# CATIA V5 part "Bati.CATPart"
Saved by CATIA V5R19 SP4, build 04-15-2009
Part number: Bati
Bounding box of the stored display mesh (mm): x 0 to 10, y 41.42 to 122.58, z 0 to 71.818
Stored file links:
  C:\Users\rcousturie\Desktop\EU_thinkMotion\iao\IAO_MMS_Groupe1\abergami\abergami_catiaInitial\ObjetsInitials\Bati.CATPart
  C:\Users\rcousturie\Desktop\EU_thinkMotion\iao\IAO_MMS_Groupe1\abergami\abergami_catiaInitial\ObjetsInitials\Product2.CATProduct
  C:\Users\rcousturie\Desktop\EU_thinkMotion\iao\IAO_MMS_Groupe1\abergami\abergami_catiaInitial\ObjetsInitials\Squelettedebase.CATPart
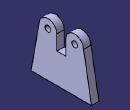
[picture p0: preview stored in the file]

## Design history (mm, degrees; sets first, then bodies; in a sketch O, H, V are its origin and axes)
External parameters (linked from other documents)
  External.Hauteursaxesbati = 60 mm
Set1
  Point1: linked copy from another document
  Point2: linked copy from another document
Body1 (main body)
  Sketch1 on yz-plane, origin (0, 0, 0), H (0, 1, 0), V (0, 0, 1)
    arc A1 centre (100, 60) radius 12 from (112, 60) to (88, 60) ccw
    point P1 (100, 60)
    arc A2 centre (64, 60) radius 12 from (76, 60) to (52, 60) ccw
    point P2 (64, 60)
    reference projected point E1 (100, 60) from Point1
    reference projected point E2 (64, 60) from Point2
    line L1 (76, 60) -> (76, 40)
    line L2 (76, 40) -> (88, 40)
    line L3 (88, 60) -> (88, 40)
    reference projected point E3 (100, 60) from Point1
    line L4 (52, 60) -> (41.4204, 0)
    line L5 (112, 60) -> (122.5796, 0)
    point P9 (112, 60)
    point P10 (122.5796, 0)
    line L6 (122.5796, 0) -> (41.4204, 0)
    radius A2 = 12
    radius A1 = 12
    distance P1 E1 = 0
    distance P2 E2 = 0
    distance L2 E3 = 20
    distance P9 L6 = 60 {= External.Hauteursaxesbati}
    angle L5 L6 = 80
    angle L4 L6 = 80
    vertical: L1 V
    horizontal: L2 H, L6 H
    tangency: L3 A1
    coincidence: P10 H
  Pad1: profile Sketch1, direction (1, 0, 0), length 10
  Sketch2 on end face of Pad1, origin (10, 100, 60), H (0, 1, 0), V (0, 0, 1)
    point P1 (0, 0)
    reference projected point E1 (0, 0) from Point1
    coincidence: E1 P1
  Hole1: placed by Sketch2, at (10, 100, 60) direction (-1, 0, 0), diameter 8, depth 10
  Sketch3 on end face of Pad1, origin (10, 0, 0), H (0, 1, 0), V (0, 0, 1)
    circle A1 centre (64, 60) radius 4
    point P1 (64, 60)
    reference projected point E1 (64, 60) from Point2
    radius A1 = 4
    distance P1 E1 = 0
  Pocket1: profile Sketch3, direction (-1, 0, 0), through (limit type 6)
